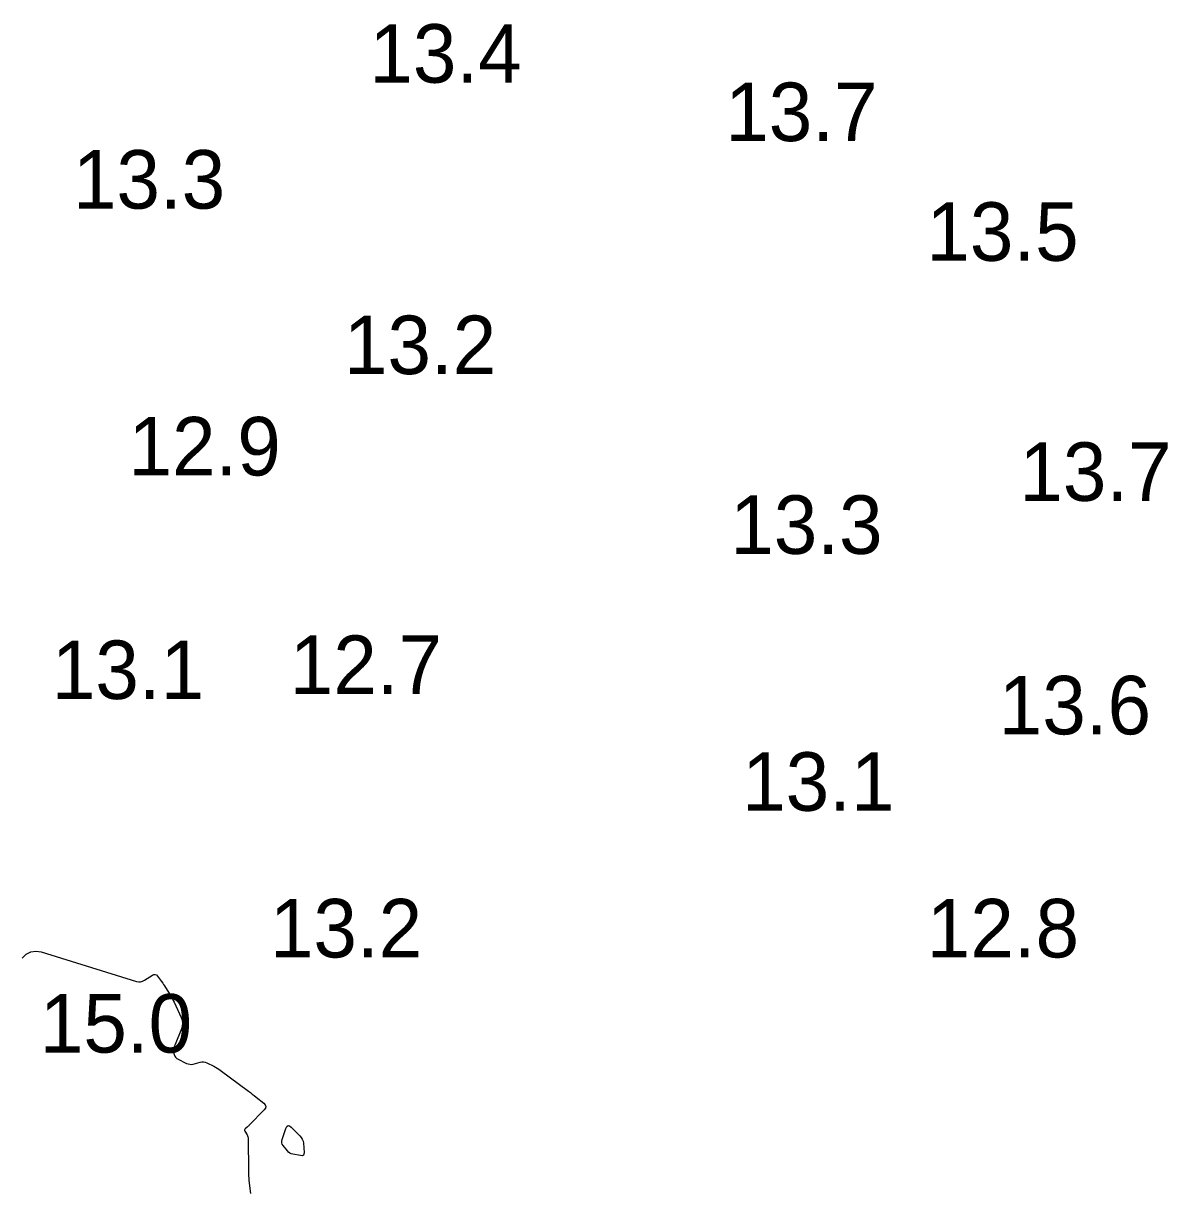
# Model space of a CAD drawing. Extents: x 1023796 to 1112670, y 656573 to 837340.
# Drawn here: x 1101329.3 to 1101427.1, y 688447 to 688546.5 of the extents above; entities that cross this region are included whole.
import ezdxf

# ---------------------------------------------------------------- set-up
doc = ezdxf.new("R2010")
doc.units = 0
doc.layers.add('V-CHAN-CONT-15FT', color=7, linetype='Continuous')
doc.layers.add('V-TOPO-SOUN', color=7, linetype='Continuous')

msp = doc.modelspace()

# ---------------------------------------------------------------- linework, layer by layer
at = {"layer": 'V-CHAN-CONT-15FT'}
msp.add_lwpolyline([(1101329.194, 688466.647), (1101329.529, 688466.999), (1101329.911, 688467.206), (1101330.341, 688467.268), (1101330.819, 688467.186), (1101338.966, 688464.677), (1101339.141, 688464.642), (1101339.31, 688464.645), (1101339.474, 688464.687), (1101339.633, 688464.768), (1101340.32, 688465.208), (1101340.441, 688465.264), (1101340.552, 688465.269), (1101340.654, 688465.225), (1101340.748, 688465.13), (1101341.103, 688464.653), (1101341.19, 688464.532), (1101341.275, 688464.41), (1101341.356, 688464.286), (1101341.436, 688464.16), (1101341.832, 688463.515), (1101341.921, 688463.364), (1101342.007, 688463.211), (1101342.087, 688463.055), (1101342.164, 688462.897), (1101342.773, 688461.586), (1101342.857, 688461.349), (1101342.889, 688461.111), (1101342.869, 688460.871), (1101342.798, 688460.63), (1101342.258, 688459.288), (1101342.236, 688459.234), (1101342.213, 688459.18), (1101342.191, 688459.127), (1101342.167, 688459.073), (1101342.074, 688458.86), (1101342.056, 688458.806), (1101342.051, 688458.753), (1101342.057, 688458.7), (1101342.075, 688458.646), (1101342.239, 688458.28), (1101342.28, 688458.206), (1101342.331, 688458.143), (1101342.393, 688458.089), (1101342.465, 688458.046), (1101343.222, 688457.67), (1101343.361, 688457.616), (1101343.503, 688457.588), (1101343.647, 688457.587), (1101343.793, 688457.613), (1101344.386, 688457.769), (1101344.533, 688457.795), (1101344.677, 688457.794), (1101344.819, 688457.767), (1101344.958, 688457.712), (1101345.556, 688457.418), (1101345.7, 688457.343), (1101345.84, 688457.262), (1101345.976, 688457.175), (1101346.108, 688457.081), (1101348.516, 688455.292), (1101348.682, 688455.167), (1101348.848, 688455.04), (1101349.012, 688454.913), (1101349.176, 688454.784), (1101349.827, 688454.264), (1101349.951, 688454.132), (1101349.998, 688453.994), (1101349.969, 688453.852), (1101349.862, 688453.705), (1101348.585, 688452.387), (1101348.543, 688452.345), (1101348.501, 688452.304), (1101348.458, 688452.263), (1101348.414, 688452.224), (1101348.238, 688452.066), (1101348.203, 688452.025), (1101348.187, 688451.981), (1101348.19, 688451.934), (1101348.211, 688451.885), (1101348.408, 688451.554), (1101348.446, 688451.48), (1101348.473, 688451.403), (1101348.489, 688451.324), (1101348.495, 688451.241), (1101348.513, 688448.439), (1101348.517, 688448.247), (1101348.526, 688448.056), (1101348.541, 688447.865), (1101348.562, 688447.675), (1101348.699, 688446.553)], dxfattribs=at)
msp.add_lwpolyline([(1101353.124, 688451.186), (1101353.182, 688451.02), (1101353.211, 688450.841), (1101353.271, 688450.047), (1101353.262, 688449.91), (1101353.21, 688449.821), (1101353.116, 688449.779), (1101352.979, 688449.785), (1101352.32, 688449.908), (1101352.182, 688449.946), (1101352.057, 688450.006), (1101351.946, 688450.088), (1101351.848, 688450.191), (1101351.482, 688450.65), (1101351.408, 688450.768), (1101351.369, 688450.892), (1101351.364, 688451.022), (1101351.395, 688451.157), (1101351.727, 688452.116), (1101351.808, 688452.277), (1101351.911, 688452.348), (1101352.034, 688452.329), (1101352.177, 688452.219), (1101352.92, 688451.477), (1101353.037, 688451.338)], close=True, dxfattribs=at)

# ---------------------------------------------------------------- texts
at = {"layer": 'V-TOPO-SOUN'}
for s, p in [('13.4 ', (1101358.852, 688541.46)), ('13.7 ', (1101389.262, 688536.47)), ('13.3 ', (1101333.522, 688530.7)), ('13.5 ', (1101406.445, 688526.24)), ('13.2 ', (1101356.682, 688516.56)), ('12.9 ', (1101338.272, 688507.9)), ('13.7 ', (1101414.392, 688505.73)), ('13.3 ', (1101389.692, 688501.2)), ('13.1 ', (1101331.717, 688488.8)), ('12.7 ', (1101352.052, 688489.23)), ('13.6 ', (1101412.634, 688485.78)), ('13.1 ', (1101390.707, 688479.25)), ('13.2 ', (1101350.352, 688466.72)), ('12.8 ', (1101406.482, 688466.72)), ('15.0 ', (1101330.693, 688458.59))]:
    msp.add_text(s, height=5, dxfattribs=at).set_placement(p)

doc.saveas('drawing.dxf')
